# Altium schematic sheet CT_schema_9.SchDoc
size 287 x 160 mm
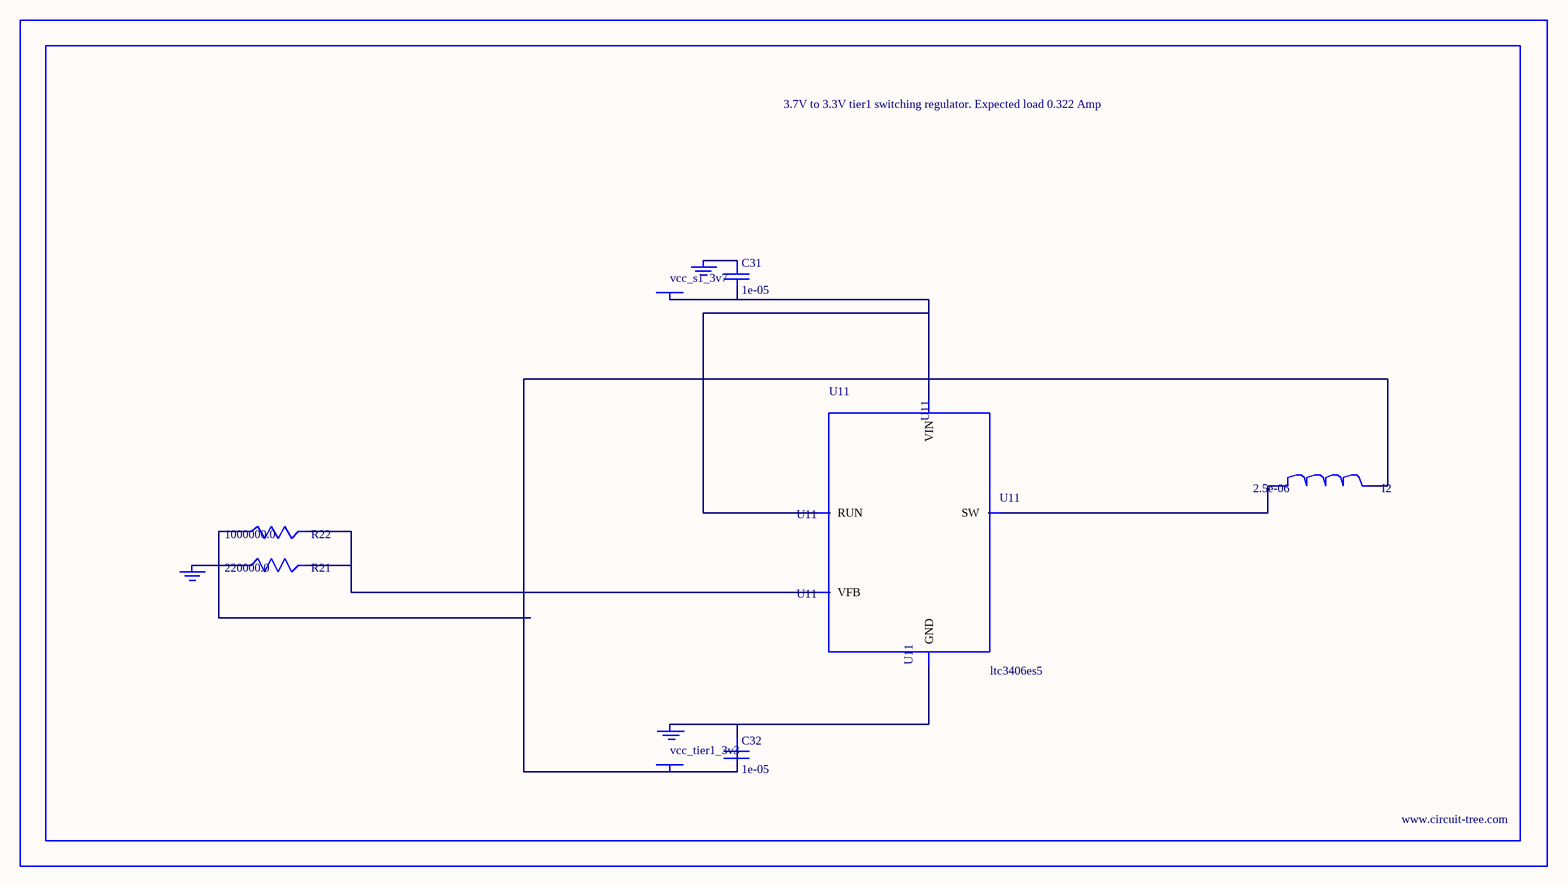
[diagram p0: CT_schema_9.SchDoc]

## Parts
BORDER8  (no value)
C31  1e-05  [C0805]
C32  1e-05  [C0805]
GND_INSTANCE_8_0  (no value)
GND_INSTANCE_8_1  (no value)
GND_INSTANCE_8_2  (no value)
I2  2.5e-06  [DR1040]
POWER_INSTANCE_8_0  vcc_tier1_3v3
POWER_INSTANCE_8_1  vcc_s1_3v7
R21  220000.0  [R0603]
R22  1000000.0  [R0603]
U11  ltc3406es5  [TSOT-23-5]

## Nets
NetC31_1: C31.1 GND_INSTANCE_8_1.0(GND)
NetC31_2: C31.2 POWER_INSTANCE_8_1.0(PWR) U11.1(RUN) U11.4(VIN)
NetC32_1: C32.1 GND_INSTANCE_8_0.0(GND) U11.2(GND)
NetC32_2: C32.2 I2.2 POWER_INSTANCE_8_0.0(PWR) R22.1
NetGND_INSTANCE_8_2_0: GND_INSTANCE_8_2.0(GND) R21.1
NetI2_1: I2.1 U11.3(SW)
NetR21_2: R21.2 R22.2 U11.5(VFB)

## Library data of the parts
BORDER8 = BORDER_PAGE8
C31 C32 = C0805C106K8RACTU
GND_INSTANCE_8_0-GND_INSTANCE_8_2 = GND
I2 = DR1040-2R5-R
POWER_INSTANCE_8_0 POWER_INSTANCE_8_1 = PWR
R21 = RC0603JR-07220KL
R22 = RC0603JR-071ML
